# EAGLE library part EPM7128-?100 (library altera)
EPM70128 MAX 7000 family
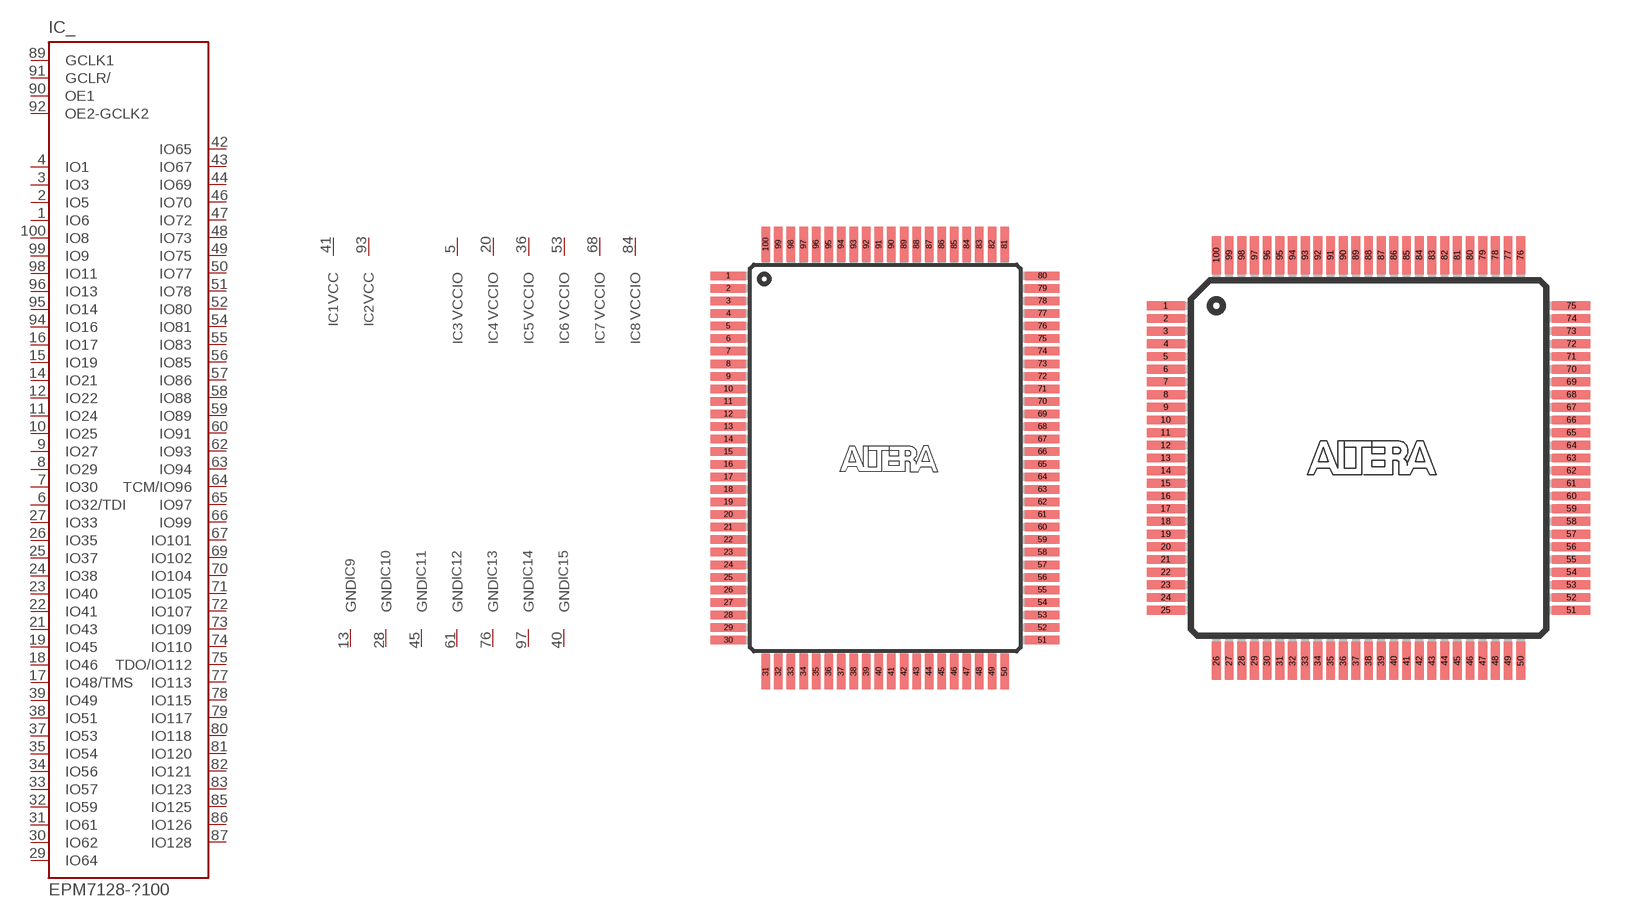
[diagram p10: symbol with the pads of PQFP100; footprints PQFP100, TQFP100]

Designator prefix IC; gates _=7128P100 1=VCC 2=VCC 3=VCCIO 4=VCCIO 5=VCCIO 6=VCCIO 7=VCCIO 8=VCCIO 9=GND 10=GND 11=GND 12=GND 13=GND 14=GND 15=GND 16=GND

## EPM7128-P100 (MPN: EPM7128SQC100-7N; OC_FARNELL: 1549424; OC_NEWARK: 51R0530)  [PQFP100]
1  _:IO6
2  _:IO5
3  _:IO3
4  _:IO1
5  3:VCCIO  pwr
6  _:IO32/TDI
7  _:IO30
8  _:IO29
9  _:IO27
10  _:IO25
11  _:IO24
12  _:IO22
13  9:GND  pwr
14  _:IO21
15  _:IO19
16  _:IO17
17  _:IO48/TMS
18  _:IO46
19  _:IO45
20  4:VCCIO  pwr
21  _:IO43
22  _:IO41
23  _:IO40
24  _:IO38
25  _:IO37
26  _:IO35
27  _:IO33
28  10:GND  pwr
29  _:IO64
30  _:IO62
31  _:IO61
32  _:IO59
33  _:IO57
34  _:IO56
35  _:IO54
36  5:VCCIO  pwr
37  _:IO53
38  _:IO51
39  _:IO49
40  15:GND  pwr
41  1:VCC  pwr
42  _:IO65
43  _:IO67
44  _:IO69
45  11:GND  pwr
46  _:IO70
47  _:IO72
48  _:IO73
49  _:IO75
50  _:IO77
51  _:IO78
52  _:IO80
53  6:VCCIO  pwr
54  _:IO81
55  _:IO83
56  _:IO85
57  _:IO86
58  _:IO88
59  _:IO89
60  _:IO91
61  12:GND  pwr
62  _:IO93
63  _:IO94
64  _:TCM/IO96
65  _:IO97
66  _:IO99
67  _:IO101
68  7:VCCIO  pwr
69  _:IO102
70  _:IO104
71  _:IO105
72  _:IO107
73  _:IO109
74  _:IO110
75  _:TDO/IO112
76  13:GND  pwr
77  _:IO113
78  _:IO115
79  _:IO117
80  _:IO118
81  _:IO120
82  _:IO121
83  _:IO123
84  8:VCCIO  pwr
85  _:IO125
86  _:IO126
87  _:IO128
88  16:GND  pwr
89  _:GCLK1  in
90  _:OE1  in
91  _:GCLR/  in
92  _:OE2-GCLK2  in
93  2:VCC  pwr
94  _:IO16
95  _:IO14
96  _:IO13
97  14:GND  pwr
98  _:IO11
99  _:IO9
100  _:IO8

## EPM7128-T100 (MPN: EPM7128STC100-7N; OC_FARNELL: 1549427; OC_NEWARK: 51R9778)  [TQFP100]
1  _:IO3
2  _:IO1
3  3:VCCIO  pwr
4  _:IO32/TDI
5  _:IO30
6  _:IO29
7  _:IO27
8  _:IO25
9  _:IO24
10  _:IO22
11  9:GND  pwr
12  _:IO21
13  _:IO19
14  _:IO17
15  _:IO48/TMS
16  _:IO46
17  _:IO45
18  4:VCCIO  pwr
19  _:IO43
20  _:IO41
21  _:IO40
22  _:IO38
23  _:IO37
24  _:IO35
25  _:IO33
26  10:GND  pwr
27  _:IO64
28  _:IO62
29  _:IO61
30  _:IO59
31  _:IO57
32  _:IO56
33  _:IO54
34  5:VCCIO  pwr
35  _:IO53
36  _:IO51
37  _:IO49
38  16:GND  pwr
39  1:VCC  pwr
40  _:IO65
41  _:IO67
42  _:IO69
43  11:GND  pwr
44  _:IO70
45  _:IO72
46  _:IO73
47  _:IO75
48  _:IO77
49  _:IO78
50  _:IO80
51  6:VCCIO  pwr
52  _:IO81
53  _:IO83
54  _:IO85
55  _:IO86
56  _:IO88
57  _:IO89
58  _:IO91
59  12:GND  pwr
60  _:IO93
61  _:IO94
62  _:TCM/IO96
63  _:IO97
64  _:IO99
65  _:IO101
66  7:VCCIO  pwr
67  _:IO102
68  _:IO104
69  _:IO105
70  _:IO107
71  _:IO109
72  _:IO110
73  _:TDO/IO112
74  13:GND  pwr
75  _:IO113
76  _:IO115
77  _:IO117
78  _:IO118
79  _:IO120
80  _:IO121
81  _:IO123
82  8:VCCIO  pwr
83  _:IO125
84  _:IO126
85  _:IO128
86  14:GND  pwr
87  _:GCLK1  in
88  _:OE1  in
89  _:GCLR/  in
90  _:OE2-GCLK2  in
91  2:VCC  pwr
92  _:IO16
93  _:IO14
94  _:IO13
95  15:GND  pwr
96  _:IO11
97  _:IO9
98  _:IO8
99  _:IO6
100  _:IO5

## Footprint PQFP100 (pad centres in mm)
Plastic Quad Flat Pack
smd 1.8 x 0.44: 1 -8.125,9.425; 2 -8.125,8.775; 3 -8.125,8.125; 4 -8.125,7.475; 5 -8.125,6.825; 6 -8.125,6.175; 7 -8.125,5.525; 8 -8.125,4.875; 9 -8.125,4.225; 10 -8.125,3.575; 11 -8.125,2.925; 12 -8.125,2.275; 13 -8.125,1.625; 14 -8.125,0.975; 15 -8.125,0.325; 16 -8.125,-0.325; 17 -8.125,-0.975; 18 -8.125,-1.625; 19 -8.125,-2.275; 20 -8.125,-2.925; 21 -8.125,-3.575; 22 -8.125,-4.225; 23 -8.125,-4.875; 24 -8.125,-5.525; 25 -8.125,-6.175; 26 -8.125,-6.825; 27 -8.125,-7.475; 28 -8.125,-8.125; 29 -8.125,-8.775; 30 -8.125,-9.425; 51 8.125,-9.425; 52 8.125,-8.775; 53 8.125,-8.125; 54 8.125,-7.475; 55 8.125,-6.825; 56 8.125,-6.175; 57 8.125,-5.525; 58 8.125,-4.875; 59 8.125,-4.225; 60 8.125,-3.575; 61 8.125,-2.925; 62 8.125,-2.275; 63 8.125,-1.625; 64 8.125,-0.975; 65 8.125,-0.325; 66 8.125,0.325; 67 8.125,0.975; 68 8.125,1.625; 69 8.125,2.275; 70 8.125,2.925; 71 8.125,3.575; 72 8.125,4.225; 73 8.125,4.875; 74 8.125,5.525; 75 8.125,6.175; 76 8.125,6.825; 77 8.125,7.475; 78 8.125,8.125; 79 8.125,8.775; 80 8.125,9.425
smd 0.44 x 1.8: 31 -6.175,-11.05; 32 -5.525,-11.05; 33 -4.875,-11.05; 34 -4.225,-11.05; 35 -3.575,-11.05; 36 -2.925,-11.05; 37 -2.275,-11.05; 38 -1.625,-11.05; 39 -0.975,-11.05; 40 -0.325,-11.05; 41 0.325,-11.05; 42 0.975,-11.05; 43 1.625,-11.05; 44 2.275,-11.05; 45 2.925,-11.05; 46 3.575,-11.05; 47 4.225,-11.05; 48 4.875,-11.05; 49 5.525,-11.05; 50 6.175,-11.05; 81 6.175,11.05; 82 5.525,11.05; 83 4.875,11.05; 84 4.225,11.05; 85 3.575,11.05; 86 2.925,11.05; 87 2.275,11.05; 88 1.625,11.05; 89 0.975,11.05; 90 0.325,11.05; 91 -0.325,11.05; 92 -0.975,11.05; 93 -1.625,11.05; 94 -2.275,11.05; 95 -2.925,11.05; 96 -3.575,11.05; 97 -4.225,11.05; 98 -4.875,11.05; 99 -5.525,11.05; 100 -6.175,11.05

## Footprint TQFP100 (pad centres in mm)
Plastic Thin Quad Flat Pack
smd 1.5 x 0.35: 1 -8,6; 2 -8,5.5; 3 -8,5; 4 -8,4.5; 5 -8,4; 6 -8,3.5; 7 -8,3; 8 -8,2.5; 9 -8,2; 10 -8,1.5; 11 -8,1; 12 -8,0.5; 13 -8,0; 14 -8,-0.5; 15 -8,-1; 16 -8,-1.5; 17 -8,-2; 18 -8,-2.5; 19 -8,-3; 20 -8,-3.5; 21 -8,-4; 22 -8,-4.5; 23 -8,-5; 24 -8,-5.5; 25 -8,-6; 51 8,-6; 52 8,-5.5; 53 8,-5; 54 8,-4.5; 55 8,-4; 56 8,-3.5; 57 8,-3; 58 8,-2.5; 59 8,-2; 60 8,-1.5; 61 8,-1; 62 8,-0.5; 63 8,0; 64 8,0.5; 65 8,1; 66 8,1.5; 67 8,2; 68 8,2.5; 69 8,3; 70 8,3.5; 71 8,4; 72 8,4.5; 73 8,5; 74 8,5.5; 75 8,6
smd 0.35 x 1.5: 26 -6,-8; 27 -5.5,-8; 28 -5,-8; 29 -4.5,-8; 30 -4,-8; 31 -3.5,-8; 32 -3,-8; 33 -2.5,-8; 34 -2,-8; 35 -1.5,-8; 36 -1,-8; 37 -0.5,-8; 38 0,-8; 39 0.5,-8; 40 1,-8; 41 1.5,-8; 42 2,-8; 43 2.5,-8; 44 3,-8; 45 3.5,-8; 46 4,-8; 47 4.5,-8; 48 5,-8; 49 5.5,-8; 50 6,-8; 76 6,8; 77 5.5,8; 78 5,8; 79 4.5,8; 80 4,8; 81 3.5,8; 82 3,8; 83 2.5,8; 84 2,8; 85 1.5,8; 86 1,8; 87 0.5,8; 88 0,8; 89 -0.5,8; 90 -1,8; 91 -1.5,8; 92 -2,8; 93 -2.5,8; 94 -3,8; 95 -3.5,8; 96 -4,8; 97 -4.5,8; 98 -5,8; 99 -5.5,8; 100 -6,8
